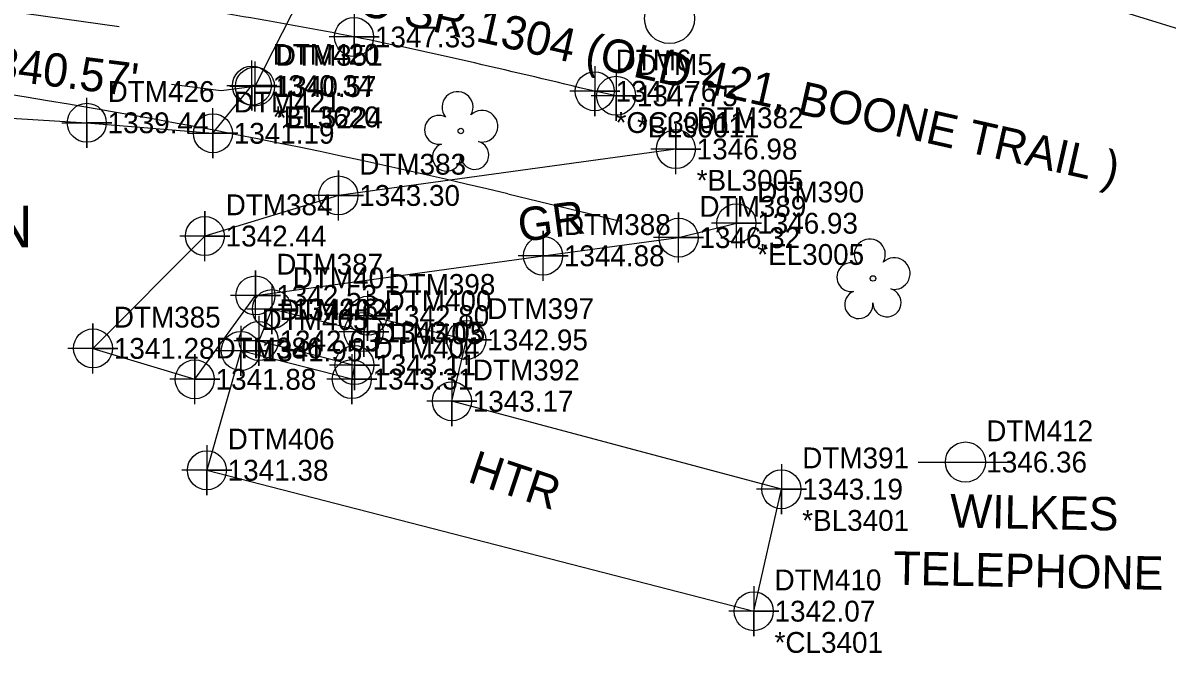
# Model space of a CAD drawing. Extents: x 1303760 to 1305114, y 904598 to 905144.
# Drawn here: x 1304493.6 to 1304630.9, y 904715.1 to 904790.7 of the extents above; entities that cross this region are included whole.
import ezdxf

# ---------------------------------------------------------------- set-up
doc = ezdxf.new("R2010")
doc.units = 0
for name, color, linetype in [('Exist Building', 7, 'Continuous'), ('Exist Building Cogo Elevation', 7, 'Continuous'), ('Exist Building Cogo Number', 7, 'Continuous'), ('Exist Building Cogo Point CELL', 7, 'Continuous'), ('Exist Building Text', 7, 'Continuous'), ('Exist Horizontal Alignment Point', 7, 'Continuous'), ('Exist Hydro Jurisdictional Stream or Body of Water', 7, 'Continuous'), ('Exist Hydro Stream or Body of Water Cogo Comment', 7, 'Continuous'), ('Exist Hydro Stream or Body of Water Cogo Elevation', 7, 'Continuous'), ('Exist Hydro Stream or Body of Water Cogo Number', 7, 'Continuous'), ('Exist Hydro Stream or Body of Water Cogo Point CELL', 7, 'Continuous'), ('Exist Property Owner Text', 7, 'Continuous'), ('Exist Right of Way Line', 7, 'Continuous'), ('Exist Roads EOP', 7, 'Continuous'), ('Exist Roads EOP Cogo Comment', 7, 'Continuous'), ('Exist Roads EOP Cogo Elevation', 7, 'Continuous'), ('Exist Roads EOP Cogo Number', 7, 'Continuous'), ('Exist Roads EOP Cogo Point CELL', 7, 'Continuous'), ('Exist Roads EOP Text', 7, 'Continuous'), ('Exist Roads Soil', 7, 'Continuous'), ('Exist Roads Soil Cogo Comment', 7, 'Continuous'), ('Exist Roads Soil Cogo Elevation', 7, 'Continuous'), ('Exist Roads Soil Cogo Number', 7, 'Continuous'), ('Exist Roads Soil Cogo Point CELL', 7, 'Continuous'), ('Exist Roads Soil Text', 7, 'Continuous'), ('Exist Structure Minor Pipes CMP 24 Inch', 7, 'Continuous'), ('Exist Structure Minor Pipes CMP 24 Inch Cogo Comment', 7, 'Continuous'), ('Exist Structure Minor Pipes CMP 24 Inch Cogo Elevation', 7, 'Continuous'), ('Exist Structure Minor Pipes CMP 24 Inch Cogo Number', 7, 'Continuous'), ('Exist Structure Minor Pipes CMP 24 Inch Cogo Point CELL', 7, 'Continuous'), ('Exist Structure Minor Pipes CMP 24 Inch Invert', 7, 'Continuous'), ('Exist Structure Minor Pipes RCP 18 Inch', 7, 'Continuous'), ('Exist Utilities Telephone Pole CELL', 7, 'Continuous'), ('Exist Utilities Telephone Pole Cogo Elevation', 7, 'Continuous'), ('Exist Utilities Telephone Pole Cogo Number', 7, 'Continuous'), ('Exist Utilities Telephone Pole Text', 7, 'Continuous'), ('Exist Utilities Telephone UG FO', 7, 'Continuous'), ('Exist Vegetation Tree CELL', 7, 'Continuous')]:
    doc.layers.add(name, color=color, linetype=linetype)

msp = doc.modelspace()

# ---------------------------------------------------------------- linework, layer by layer
at = {"layer": 'Exist Building'}
msp.add_lwpolyline([(1304584.63, 904734.78), (1304545.11, 904745.34), (1304546.84, 904752.69), (1304535, 904755.6), (1304534.53, 904753.65), (1304523.51, 904756.39), (1304521.93, 904752.58), (1304533.42, 904749.68), (1304533.1, 904747.99), (1304519.78, 904751.38), (1304515.71, 904737.06), (1304581.31, 904720.15), (1304584.63, 904734.78)], dxfattribs=at)
at = {"layer": 'Exist Building Cogo Point CELL'}
for points in [[(1304523.51, 904759.39), (1304523.51, 904753.39), (1304523.51, 904756.39), (1304526.51, 904756.39), (1304520.51, 904756.39)], [(1304535, 904758.6), (1304535, 904752.6), (1304535, 904755.6), (1304538, 904755.6), (1304532, 904755.6)], [(1304534.53, 904756.65), (1304534.53, 904750.65), (1304534.53, 904753.65), (1304537.53, 904753.65), (1304531.53, 904753.65)], [(1304519.78, 904754.38), (1304519.78, 904748.38), (1304519.78, 904751.38), (1304522.78, 904751.38), (1304516.78, 904751.38)], [(1304521.93, 904755.58), (1304521.93, 904749.58), (1304521.93, 904752.58), (1304524.93, 904752.58), (1304518.93, 904752.58)], [(1304546.84, 904755.69), (1304546.84, 904749.69), (1304546.84, 904752.69), (1304549.84, 904752.69), (1304543.84, 904752.69)], [(1304533.42, 904752.68), (1304533.42, 904746.68), (1304533.42, 904749.68), (1304536.42, 904749.68), (1304530.42, 904749.68)], [(1304533.1, 904750.99), (1304533.1, 904744.99), (1304533.1, 904747.99), (1304536.1, 904747.99), (1304530.1, 904747.99)], [(1304545.11, 904748.34), (1304545.11, 904742.34), (1304545.11, 904745.34), (1304548.11, 904745.34), (1304542.11, 904745.34)], [(1304515.71, 904740.06), (1304515.71, 904734.06), (1304515.71, 904737.06), (1304518.71, 904737.06), (1304512.71, 904737.06)], [(1304584.63, 904737.78), (1304584.63, 904731.78), (1304584.63, 904734.78), (1304587.63, 904734.78), (1304581.63, 904734.78)], [(1304581.31, 904723.15), (1304581.31, 904717.15), (1304581.31, 904720.15), (1304584.31, 904720.15), (1304578.31, 904720.15)]]:
    msp.add_lwpolyline(points, dxfattribs=at)
for centre in [(1304523.51, 904756.39), (1304535, 904755.6), (1304534.53, 904753.65), (1304521.93, 904752.58), (1304546.84, 904752.69), (1304519.78, 904751.38), (1304533.42, 904749.68), (1304533.1, 904747.99), (1304545.11, 904745.34), (1304515.71, 904737.06), (1304584.63, 904734.78), (1304581.31, 904720.15)]:
    msp.add_circle(centre, 2.34, dxfattribs=at)
at = {"layer": 'Exist Horizontal Alignment Point'}
msp.add_line((1304574.13, 904790.55), (1304574.14, 904790.55), dxfattribs=at)
msp.add_circle((1304571.22, 904791.25), 3, dxfattribs=at)
at = {"layer": 'Exist Hydro Jurisdictional Stream or Body of Water'}
msp.add_lwpolyline([(1304394.44, 904759.18), (1304399.94, 904767.1), (1304425.07, 904781.67), (1304461.07, 904781.24), (1304501.31, 904778.75), (1304516.44, 904777.49), (1304521.11, 904783.21)], dxfattribs=at)
at = {"layer": 'Exist Hydro Stream or Body of Water Cogo Point CELL'}
for points in [[(1304518.11, 904783.21), (1304524.11, 904783.21), (1304521.11, 904783.21), (1304521.11, 904780.21), (1304521.11, 904786.21)], [(1304498.31, 904778.75), (1304504.31, 904778.75), (1304501.31, 904778.75), (1304501.31, 904775.75), (1304501.31, 904781.75)], [(1304513.44, 904777.49), (1304519.44, 904777.49), (1304516.44, 904777.49), (1304516.44, 904774.49), (1304516.44, 904780.49)]]:
    msp.add_lwpolyline(points, dxfattribs=at)
for centre in [(1304521.11, 904783.21), (1304501.31, 904778.75), (1304516.44, 904777.49)]:
    msp.add_circle(centre, 2.34, dxfattribs=at)
at = {"layer": 'Exist Right of Way Line'}
msp.add_line((1304551.81, 904770.22), (1304565.36, 904766.95), dxfattribs=at)
msp.add_arc((1304372.37, 904026.26), 765.29, 76.43947, 88.71327, dxfattribs=at)
at = {"layer": 'Exist Roads EOP'}
msp.add_line((1304564.81, 904781.99), (1304562.24, 904782.53), dxfattribs=at)
msp.add_spline([(1304562.24, 904782.53), (1304533.37, 904789.05), (1304505.02, 904793.93), (1304455.89, 904800.99), (1304407.77, 904804.89), (1304387.95, 904804.96)], degree=3, dxfattribs=at)
at = {"layer": 'Exist Roads EOP Cogo Point CELL'}
for points in [[(1304533.37, 904792.05), (1304533.37, 904786.05), (1304533.37, 904789.05), (1304536.37, 904789.05), (1304530.37, 904789.05)], [(1304562.24, 904785.53), (1304562.24, 904779.53), (1304562.24, 904782.53), (1304565.24, 904782.53), (1304559.24, 904782.53)], [(1304564.81, 904784.99), (1304564.81, 904778.99), (1304564.81, 904781.99), (1304567.81, 904781.99), (1304561.81, 904781.99)]]:
    msp.add_lwpolyline(points, dxfattribs=at)
for centre in [(1304533.37, 904789.05), (1304562.24, 904782.53), (1304564.81, 904781.99)]:
    msp.add_circle(centre, 2.34, dxfattribs=at)
at = {"layer": 'Exist Roads Soil'}
msp.add_lwpolyline([(1304571.97, 904775.6), (1304531.49, 904770.03), (1304515.47, 904765.16), (1304502.05, 904751.68), (1304514.26, 904747.97), (1304521.54, 904758.03), (1304556.04, 904762.79), (1304572.3, 904764.97), (1304579.23, 904766.7)], dxfattribs=at)
at = {"layer": 'Exist Roads Soil Cogo Point CELL'}
for points in [[(1304571.97, 904772.6), (1304571.97, 904778.6), (1304571.97, 904775.6), (1304574.97, 904775.6), (1304568.97, 904775.6)], [(1304531.49, 904767.03), (1304531.49, 904773.03), (1304531.49, 904770.03), (1304534.49, 904770.03), (1304528.49, 904770.03)], [(1304579.23, 904763.7), (1304579.23, 904769.7), (1304579.23, 904766.7), (1304582.23, 904766.7), (1304576.23, 904766.7)], [(1304515.47, 904762.16), (1304515.47, 904768.16), (1304515.47, 904765.16), (1304518.47, 904765.16), (1304512.47, 904765.16)], [(1304572.3, 904761.97), (1304572.3, 904767.97), (1304572.3, 904764.97), (1304575.3, 904764.97), (1304569.3, 904764.97)], [(1304556.04, 904759.79), (1304556.04, 904765.79), (1304556.04, 904762.79), (1304559.04, 904762.79), (1304553.04, 904762.79)], [(1304521.54, 904755.03), (1304521.54, 904761.03), (1304521.54, 904758.03), (1304524.54, 904758.03), (1304518.54, 904758.03)], [(1304502.05, 904748.68), (1304502.05, 904754.68), (1304502.05, 904751.68), (1304505.05, 904751.68), (1304499.05, 904751.68)], [(1304514.26, 904744.97), (1304514.26, 904750.97), (1304514.26, 904747.97), (1304517.26, 904747.97), (1304511.26, 904747.97)]]:
    msp.add_lwpolyline(points, dxfattribs=at)
for centre in [(1304571.97, 904775.6), (1304531.49, 904770.03), (1304579.23, 904766.7), (1304515.47, 904765.16), (1304572.3, 904764.97), (1304556.04, 904762.79), (1304521.54, 904758.03), (1304502.05, 904751.68), (1304514.26, 904747.97)]:
    msp.add_circle(centre, 2.34, dxfattribs=at)
at = {"layer": 'Exist Structure Minor Pipes CMP 24 Inch'}
msp.add_line((1304539.97, 904819.6), (1304521.48, 904783.1), dxfattribs=at)
at = {"layer": 'Exist Structure Minor Pipes CMP 24 Inch Cogo Point CELL'}
msp.add_lwpolyline([(1304521.48, 904786.1), (1304521.48, 904780.1), (1304521.48, 904783.1), (1304524.48, 904783.1), (1304518.48, 904783.1)], dxfattribs=at)
msp.add_circle((1304521.48, 904783.1), 2.34, dxfattribs=at)
at = {"layer": 'Exist Structure Minor Pipes CMP 24 Inch Invert'}
msp.add_lwpolyline([(1304521.48, 904783.1), (1304517.43, 904782.59), (1304511.48, 904783.34)], dxfattribs=at)
at = {"layer": 'Exist Structure Minor Pipes RCP 18 Inch'}
msp.add_line((1304638.84, 904787.94), (1304571.92, 904808.74), dxfattribs=at)
at = {"layer": 'Exist Utilities Telephone Pole CELL'}
for p, q in [((1304601.03, 904738.04), (1304612.37, 904738.04)), ((1304606.71, 904738.04), (1304606.71, 904738.04))]:
    msp.add_line(p, q, dxfattribs=at)
msp.add_circle((1304606.71, 904738.04), 2.41, dxfattribs=at)
at = {"layer": 'Exist Utilities Telephone UG FO'}
msp.add_lwpolyline([(1304409.35, 904794.32), (1304412.47, 904801.46), (1304445.01, 904798.79), (1304505.19, 904790.31)], dxfattribs=at)
at = {"layer": 'Exist Vegetation Tree CELL'}
for p, q in [((1304546.17, 904777.76), (1304546.17, 904777.76)), ((1304595.62, 904760.07), (1304595.62, 904760.07))]:
    msp.add_line(p, q, dxfattribs=at)
for centre in [(1304546.17, 904777.76), (1304595.62, 904760.07)]:
    msp.add_circle(centre, 0.326, dxfattribs=at)
for centre, radius, start, end in [((1304545.78, 904780.63), 1.86, 330.1651, 219.7134), ((1304543.56, 904777.91), 1.73, 62.6636, 279.3457), ((1304548.72, 904778.34), 1.9, 257.1011, 134.1999), ((1304547.84, 904774.86), 1.7, 181.2822, 74.56), ((1304544.46, 904774.63), 1.69, 111.5671, 6.231), ((1304595.24, 904762.95), 1.86, 330.1651, 219.7134), ((1304593.02, 904760.23), 1.73, 62.6636, 279.3457), ((1304598.17, 904760.66), 1.9, 257.1011, 134.1999), ((1304593.92, 904756.95), 1.69, 111.5671, 6.231), ((1304597.3, 904757.17), 1.7, 181.2822, 74.56)]:
    msp.add_arc(centre, radius, start, end, dxfattribs=at)

# ---------------------------------------------------------------- texts
at = {"layer": 'Exist Building Cogo Elevation'}
for s, p in [('1342.64', (1304526.01, 904755.14)), ('1342.80', (1304537.5, 904754.35)), ('1343.05', (1304537.03, 904752.4)), ('1342.63', (1304524.43, 904751.33)), ('1342.95', (1304549.34, 904751.45)), ('1341.95', (1304522.28, 904750.13)), ('1343.11', (1304535.92, 904748.44)), ('1343.31', (1304535.6, 904746.74)), ('1343.17', (1304547.61, 904744.09)), ('1341.38', (1304518.21, 904735.81)), ('1343.19', (1304587.13, 904733.54)), ('*BL3401', (1304587.13, 904729.79)), ('1342.07', (1304583.81, 904718.9)), ('*CL3401', (1304583.81, 904715.15))]:
    msp.add_text(s, height=2.5, dxfattribs=at).set_placement(p)
at = {"layer": 'Exist Building Cogo Number'}
for s, p in [('DTM401', (1304526.01, 904758.89)), ('DTM398', (1304537.5, 904758.1)), ('DTM400', (1304537.03, 904756.15)), ('DTM402', (1304524.43, 904755.08)), ('DTM397', (1304549.34, 904755.2)), ('DTM405', (1304522.28, 904753.88)), ('DTM403', (1304535.92, 904752.19)), ('DTM404', (1304535.6, 904750.49)), ('DTM392', (1304547.61, 904747.84)), ('DTM406', (1304518.21, 904739.56)), ('DTM391', (1304587.13, 904737.29)), ('DTM410', (1304583.81, 904722.65))]:
    msp.add_text(s, height=2.5, dxfattribs=at).set_placement(p)
at = {"layer": 'Exist Building Text'}
msp.add_text('HTR', height=4, rotation=341.5464, dxfattribs=at).set_placement((1304546.85, 904735.72))
at = {"layer": 'Exist Hydro Stream or Body of Water Cogo Comment'}
msp.add_text('*BL3620', height=2.5, dxfattribs=at).set_placement((1304523.61, 904778.21))
at = {"layer": 'Exist Hydro Stream or Body of Water Cogo Elevation'}
for s, p in [('1340.34', (1304523.61, 904781.96)), ('1339.44', (1304503.81, 904777.5)), ('1341.19', (1304518.94, 904776.24))]:
    msp.add_text(s, height=2.5, dxfattribs=at).set_placement(p)
at = {"layer": 'Exist Hydro Stream or Body of Water Cogo Number'}
for s, p in [('DTM420', (1304523.61, 904785.71)), ('DTM426', (1304503.81, 904781.25)), ('DTM421', (1304518.94, 904779.99))]:
    msp.add_text(s, height=2.5, dxfattribs=at).set_placement(p)
at = {"layer": 'Exist Property Owner Text'}
msp.add_text('EVELYN S. VINSON', height=5, dxfattribs=at).set_placement((1304432.76, 904763.81))
at = {"layer": 'Exist Roads EOP Cogo Comment'}
for s, p in [('*OC30011', (1304564.74, 904777.53)), ('*BL30011', (1304567.31, 904776.99))]:
    msp.add_text(s, height=2.5, dxfattribs=at).set_placement(p)
at = {"layer": 'Exist Roads EOP Cogo Elevation'}
for s, p in [('1347.33', (1304535.87, 904787.8)), ('1347.76', (1304564.74, 904781.28)), ('1347.75', (1304567.31, 904780.74))]:
    msp.add_text(s, height=2.5, dxfattribs=at).set_placement(p)
at = {"layer": 'Exist Roads EOP Cogo Number'}
for s, p in [('DTM6', (1304564.74, 904785.03)), ('DTM5', (1304567.31, 904784.49))]:
    msp.add_text(s, height=2.5, dxfattribs=at).set_placement(p)
at = {"layer": 'Exist Roads EOP Text'}
msp.add_text('TO SR 1304 (OLD 421, BOONE TRAIL )', height=4, rotation=347.2711, dxfattribs=at).set_placement((1304530.44, 904792.51))
at = {"layer": 'Exist Roads Soil Cogo Comment'}
for s, p in [('*BL3005', (1304574.47, 904770.6)), ('*EL3005', (1304581.73, 904761.7))]:
    msp.add_text(s, height=2.5, dxfattribs=at).set_placement(p)
at = {"layer": 'Exist Roads Soil Cogo Elevation'}
for s, p in [('1346.98', (1304574.47, 904774.35)), ('1343.30', (1304533.99, 904768.78)), ('1346.93', (1304581.73, 904765.45)), ('1342.44', (1304517.97, 904763.91)), ('1346.32', (1304574.8, 904763.72)), ('1344.88', (1304558.54, 904761.54)), ('1342.53', (1304524.04, 904756.78)), ('1341.28', (1304504.55, 904750.43)), ('1341.88', (1304516.76, 904746.72))]:
    msp.add_text(s, height=2.5, dxfattribs=at).set_placement(p)
at = {"layer": 'Exist Roads Soil Cogo Number'}
for s, p in [('DTM382', (1304574.47, 904778.1)), ('DTM383', (1304533.99, 904772.53)), ('DTM390', (1304581.73, 904769.2)), ('DTM384', (1304517.97, 904767.66)), ('DTM389', (1304574.8, 904767.47)), ('DTM388', (1304558.54, 904765.29)), ('DTM387', (1304524.04, 904760.53)), ('DTM385', (1304504.55, 904754.18)), ('DTM386', (1304516.76, 904750.47))]:
    msp.add_text(s, height=2.5, dxfattribs=at).set_placement(p)
at = {"layer": 'Exist Roads Soil Text'}
msp.add_text('GR', height=4, rotation=7.6508, dxfattribs=at).set_placement((1304553.3, 904764.44))
at = {"layer": 'Exist Structure Minor Pipes CMP 24 Inch Cogo Comment'}
msp.add_text('*EL5224', height=2.5, dxfattribs=at).set_placement((1304523.98, 904778.1))
at = {"layer": 'Exist Structure Minor Pipes CMP 24 Inch Cogo Elevation'}
msp.add_text('1340.57', height=2.5, dxfattribs=at).set_placement((1304523.98, 904781.85))
at = {"layer": 'Exist Structure Minor Pipes CMP 24 Inch Cogo Number'}
msp.add_text('DTM351', height=2.5, dxfattribs=at).set_placement((1304523.98, 904785.6))
at = {"layer": 'Exist Structure Minor Pipes CMP 24 Inch Invert'}
msp.add_text("INV=1340.57'", height=4, rotation=352.815, dxfattribs=at).set_placement((1304475.06, 904785.91))
at = {"layer": 'Exist Utilities Telephone Pole Cogo Elevation'}
msp.add_text('1346.36', height=2.5, dxfattribs=at).set_placement((1304609.21, 904736.79))
at = {"layer": 'Exist Utilities Telephone Pole Cogo Number'}
msp.add_text('DTM412', height=2.5, dxfattribs=at).set_placement((1304609.21, 904740.54))
at = {"layer": 'Exist Utilities Telephone Pole Text'}
for s, p in [('WILKES ', (1304604.83, 904730.21)), ('TELEPHONE', (1304598.03, 904723.34))]:
    msp.add_text(s, height=4, rotation=358.8754, dxfattribs=at).set_placement(p)

doc.saveas('drawing.dxf')
